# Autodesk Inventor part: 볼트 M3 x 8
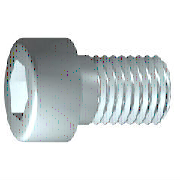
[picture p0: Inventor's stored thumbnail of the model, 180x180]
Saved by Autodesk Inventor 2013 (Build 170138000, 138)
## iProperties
IsCustomPart: 0
Created: 2012-02
Part Number: 볼트 M3 x 8
Material: 스테인리스강
Description: 6각 소켓 머리 캡 나사
Document SubType Name: Modeling
Standard: ISO 4762
Designer: mduedu
Standard Revision: Fourth edition 2004-03-01
Standards Organization: ISO
Language: ko-KR
Size Designation: M3 x 8
Categories: <MemberInstance><Categories><Category DisplayName="조임쇠" InternalName="e4da775c-781d-43d5-af7c-5136215cf5a6" Mnemonic="FSTN"><Category DisplayName="볼트" InternalN
Density: 8.08 g/cm^3
Mass: 0.955869 g
Surface Area: 1.83001 cm^2
Volume: 0.118301 cm^3
Author: mduedu
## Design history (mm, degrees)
sketch "스케치1"
  geometry: L1 (-0.867, 0)-(8, 0); L2 (8, 0)-(8, 1.5); L3 (8, 1.5)-(1.25, 1.5); L4 (1.25, 1.5)-(0.943, 1.5); L5 (0.943, 1.5)-(0, 1.5); L6 (0, 1.5)-(0, 2.75); L7 (0, 2.75)-(-3, 2.75); L8 (-3, 2.75)-(-3, 1.443); L9 (-3, 1.443)-(-1.7, 1.443); L10 (-1.7, 1.443)-(-0.867, 0); L11 (-5.2, 0)-(10.2, 0) reference; L12 (0, -0.55)-(0, 3.3) reference; L13 (1.25, 1.5)-(0, 1.5)
  constraints: 22 end point, 6 parallel, 2 collinear, 2 perpendicular, 1 horizontal, 1 point on line
  dimensions: "d1" = 6.75 distance from line of L3.end L2 (= GEL); "d2" = 0.30683 distance of L4.end L3.end (computed from GAL); "d3" = 3 distance between parallel lines of L8 L6 (= KOH); "d4" = 1.3 distance of L8.end L9.end (= INTI); "d5" = 60 deg angle of L10 L1; "d6" = 3 diameter of L3 L1 (= GD); "d7" = 3 diameter of L5 L1 (= BDM); "d8" = 2.88675 diameter of L9 L1 (= 1.1547 x SW); "d9" = 5.5 diameter of L7 L1 (= KOD); "d26" = 8 distance between parallel lines of L12 L2 (= NLG)
revolve "본체" sketch "스케치1" stored, may be unused: angle "d10" = 90 deg
sketch "스케치2"
  geometry: L1 (0, -3.85)-(0, 3.85) reference; L2 (-3.85, 0)-(3.85, 0) reference; L3 (1.443, 0)-(0.722, -1.25); L4 (0.722, -1.25)-(-0.722, -1.25); L5 (-0.722, -1.25)-(-1.443, 0); L6 (-1.443, 0)-(-0.722, 1.25); L7 (-0.722, 1.25)-(0.722, 1.25); L8 (0.722, 1.25)-(1.443, 0); 2 further points
  constraints: 12 end point, 1 coincident, 1 horizontal alignment, 1 point on line, 12 other
extrude "슬롯" join sketch "스케치2" stored distance "d11" = 10; taper "d12" = 0 deg
workplane "Work Plane1"
fillet "Fillet2" dims "d30" = 0.1 (= R)
body "Solid1"
fillet "모깎기1" dims "d17" = 0.3 (= RR)
feature "스레드" dims "d13" = 6.75 (= GEL), "d14" = 0
chamfer "모따기1" distance "d15" = 0.30673 (= -0.5 x SPD + 0.5 x GD); stored, may be unused: second distance "d16" = 0.30673 (= GUL), angle "d27" = 45 deg
other parameters: "GD" = 3 [user parameter; used in 2 equation terms], "NLG" = 8 [user parameter; used in 1 equation term], "GEL" = 6.75 [user parameter; used in 2 equation terms], "KOD" = 5.5 [user parameter; used in 1 equation term], "KOH" = 3 [user parameter; used in 1 equation term], "INTI" = 1.3 [user parameter; used in 1 equation term], "GAL" = 0.30673 (= 0.61345 x PTC) [user parameter; used in 1 equation term], "GUL" = 0.30673 (= 0.61345 x PTC) [user parameter; used in 1 equation term], "BDM" = 3 (= NND) [user parameter; used in 1 equation term], "SW" = 2.5 [user parameter; used in 2 equation terms], "RR" = 0.3 [user parameter; used in 1 equation term], "SPD" = 2.38655 (= NND - 1.2269 x PTC) [user parameter; used in 1 equation term], "d19" = 0, "d28" = 0, "d29" = 0, "R" = 0.1 [user parameter; used in 1 equation term], "TOA" = 30 deg [user parameter], "GD1" = 2.38655 (= THREADDIA - 1.2269 x PTC) [user parameter], "THREADDIA" = 3 [user parameter; used in 1 equation term], "FAWI" = 45 deg [user parameter], "PTC" = 0.5 [user parameter; used in 5 equation terms], "NND" = 3 [user parameter; used in 2 equation terms], "E0" = 2.8875 (= 1.155 x SW) [user parameter]
